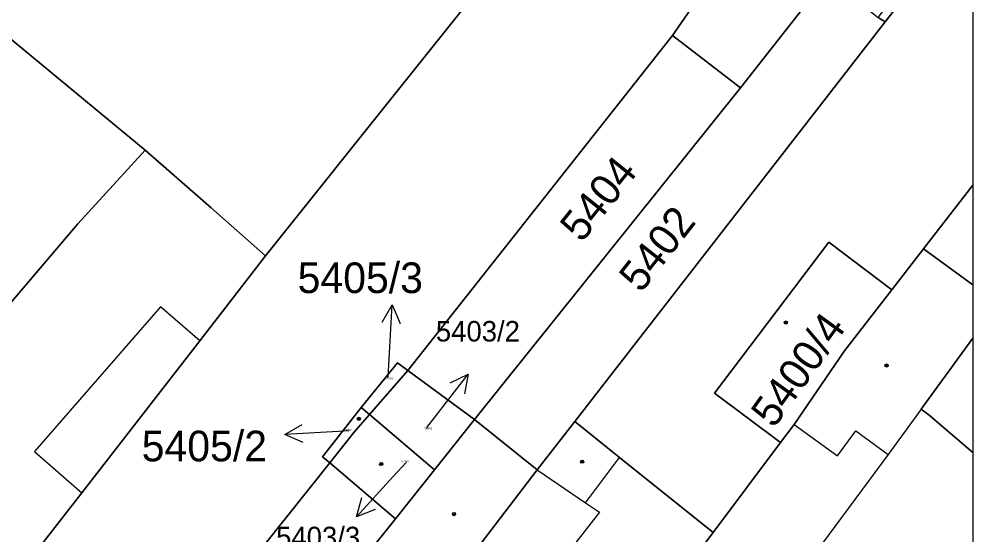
# Model space of a CAD drawing. Extents: x -596233 to -595156, y -1161235 to -1159375.
# Drawn here: x -595211.2 to -595158.2, y -1160883.5 to -1160854.9 of the extents above; entities that cross this region are included whole.
import ezdxf

# ---------------------------------------------------------------- set-up
doc = ezdxf.new("R2010")
doc.units = 0
for name, color, linetype in [('KN_CAR_KR', 7, 'Continuous'), ('KN_KULTURY', 7, 'Continuous'), ('KN_PARC_CIS_POM', 7, 'Continuous'), ('KN_PARC_CIS_POZ', 7, 'Continuous'), ('KN_PARC_CIS_STAV', 7, 'Continuous'), ('KN_PARC_PLOCHA', 7, 'Continuous'), ('PARC_C_SIPKA', 7, 'Continuous'), ('parcely_l', 7, 'Continuous')]:
    doc.layers.add(name, color=color, linetype=linetype)

msp = doc.modelspace()

# ---------------------------------------------------------------- linework, layer by layer
at = {"layer": 'KN_CAR_KR'}
for points in [[(-595203.31, -1160870.85), (-595210.3, -1160878.89)], [(-595201.13, -1160872.75), (-595203.31, -1160870.85)], [(-595161.1, -1160876.53), (-595162.94, -1160879.05)], [(-595168.15, -1160877.38), (-595165.75, -1160879.13)], [(-595165.75, -1160879.13), (-595164.73, -1160877.73)], [(-595164.73, -1160877.73), (-595162.94, -1160879.05)], [(-595210.3, -1160878.89), (-595207.67, -1160881.17)], [(-595179.73, -1160881.73), (-595177.83, -1160879.22)], [(-595162.94, -1160879.05), (-595174.72, -1160894.97)], [(-595182.4, -1160879.91), (-595179.73, -1160881.73)], [(-595179.73, -1160881.73), (-595178.94, -1160882.26)], [(-595178.94, -1160882.26), (-595188.92, -1160895.04)]]:
    msp.add_lwpolyline(points, dxfattribs=at)
at = {"layer": 'KN_KULTURY'}
for centre, radius in [((-595168.61, -1160871.73), 0.09), ((-595168.61, -1160871.73), 0.0398), ((-595163.02, -1160874.11), 0.09), ((-595163.02, -1160874.11), 0.0398), ((-595192.3, -1160877.07), 0.09), ((-595192.3, -1160877.07), 0.0398), ((-595191.06, -1160879.58), 0.09), ((-595191.06, -1160879.58), 0.0398), ((-595179.91, -1160879.45), 0.09), ((-595179.91, -1160879.45), 0.0398), ((-595187.02, -1160882.36), 0.09), ((-595187.02, -1160882.36), 0.0398)]:
    msp.add_circle(centre, radius, dxfattribs=at)
at = {"layer": 'KN_PARC_PLOCHA'}
for points in [[(-595158.2304, -1160833.5578), (-595169.34, -1160847.73), (-595174.9, -1160855.8), (-595189.59, -1160874.38), (-595190.16, -1160873.96), (-595192.17, -1160876.44), (-595194.31, -1160879.18), (-595193.91, -1160879.52), (-595201.27, -1160888.74), (-595207.27, -1160896.3), (-595216.06, -1160891.37), (-595210.02, -1160884.2), (-595207.67, -1160881.17), (-595201.13, -1160872.75), (-595197.47, -1160868.03), (-595181.99, -1160848.62), (-595180.09, -1160846.24), (-595173.37, -1160837.72), (-595168.7, -1160831.86), (-595164.04, -1160826), (-595159.37, -1160820.14), (-595158.2304, -1160818.7112)], [(-595193.38, -1160839.46), (-595185.77, -1160845.57), (-595181.99, -1160848.62), (-595197.47, -1160868.03), (-595200.5, -1160865.36), (-595204.15, -1160862.15), (-595211.84, -1160855.79), (-595218.88, -1160849.86), (-595220.43, -1160851.29), (-595224.67, -1160856), (-595227, -1160854.17), (-595228.57, -1160852.93), (-595225.27, -1160849.86), (-595204.53, -1160830.52)], [(-595158.2304, -1160837.6852), (-595158.42, -1160837.93), (-595160.07, -1160839.89), (-595161.73, -1160842.01), (-595163.37, -1160844.29), (-595165.02, -1160846.42), (-595166.67, -1160848.54), (-595168.44, -1160850.82), (-595166.29, -1160852.54), (-595171.12, -1160858.69), (-595174.9, -1160855.8), (-595169.34, -1160847.73), (-595158.2304, -1160833.5578)], [(-595158.2304, -1160848.8418), (-595163.09, -1160855.03), (-595163.48, -1160854.8), (-595161.67, -1160852.42), (-595160.02, -1160850.3), (-595158.37, -1160848.18), (-595158.2304, -1160847.9814)], [(-595158.2304, -1160864.1086), (-595160.97, -1160867.64), (-595162.73, -1160869.91), (-595166.23, -1160867.26), (-595172.57, -1160875.65), (-595168.9, -1160878.38), (-595172.65, -1160883.38), (-595177.83, -1160879.22), (-595180.32, -1160877.22), (-595163.09, -1160855.03), (-595158.2304, -1160848.8418)], [(-595163.48, -1160854.8), (-595163.09, -1160855.03), (-595180.32, -1160877.22), (-595182.4, -1160879.91), (-595185.88, -1160877.1), (-595171.12, -1160858.69), (-595166.29, -1160852.54)], [(-595204.15, -1160862.15), (-595207.89, -1160866.25), (-595223.93, -1160885.1), (-595231.86, -1160878.58), (-595217.35, -1160862.42), (-595217.51, -1160862.28), (-595211.84, -1160855.79)], [(-595171.12, -1160858.69), (-595185.88, -1160877.1), (-595189.59, -1160874.38), (-595174.9, -1160855.8)], [(-595197.47, -1160868.03), (-595201.13, -1160872.75), (-595207.67, -1160881.17), (-595210.02, -1160884.2), (-595216.06, -1160891.37), (-595223.93, -1160885.1), (-595207.89, -1160866.25), (-595204.15, -1160862.15), (-595200.5, -1160865.36)], [(-595158.2304, -1160864.1086), (-595158.2304, -1160869.6402), (-595160.97, -1160867.64)], [(-595162.73, -1160869.91), (-595165.36, -1160873.3), (-595168.15, -1160877.38), (-595168.9, -1160878.38), (-595172.57, -1160875.65), (-595166.23, -1160867.26)], [(-595158.2304, -1160869.6402), (-595158.2304, -1160872.6011), (-595161.1, -1160876.53), (-595160.66, -1160876.86), (-595158.2304, -1160878.9346), (-595158.2304, -1160894.6076), (-595160.01, -1160896.91), (-595162.85, -1160901.09), (-595168.12, -1160909.33), (-595168.15, -1160909.38), (-595188.26, -1160904.94), (-595182.91, -1160897.08), (-595176.06, -1160887.94), (-595172.65, -1160883.38), (-595168.9, -1160878.38), (-595168.15, -1160877.38), (-595165.36, -1160873.3), (-595162.73, -1160869.91), (-595160.97, -1160867.64)], [(-595158.2304, -1160872.6011), (-595158.2304, -1160878.9346), (-595160.66, -1160876.86), (-595161.1, -1160876.53)], [(-595189.59, -1160874.38), (-595191.71, -1160876.83), (-595192.17, -1160876.44), (-595190.16, -1160873.96)], [(-595185.88, -1160877.1), (-595188.11, -1160879.9), (-595191.71, -1160876.83), (-595189.59, -1160874.38)], [(-595191.71, -1160876.83), (-595192.57, -1160877.83), (-595193.91, -1160879.52), (-595194.31, -1160879.18), (-595192.17, -1160876.44)], [(-595182.4, -1160879.91), (-595188.33, -1160887.65), (-595192.94, -1160893.67), (-595197.93, -1160901.64), (-595202.6, -1160898.97), (-595197.02, -1160891.25), (-595195.01, -1160888.66), (-595194.06, -1160887.43), (-595191.99, -1160884.77), (-595190.27, -1160882.62), (-595188.11, -1160879.9), (-595185.88, -1160877.1)], [(-595188.11, -1160879.9), (-595190.27, -1160882.62), (-595193.91, -1160879.52), (-595192.57, -1160877.83), (-595191.71, -1160876.83)], [(-595172.65, -1160883.38), (-595176.06, -1160887.94), (-595182.91, -1160897.08), (-595188.26, -1160904.94), (-595197.93, -1160901.64), (-595192.94, -1160893.67), (-595188.33, -1160887.65), (-595182.4, -1160879.91), (-595180.32, -1160877.22), (-595177.83, -1160879.22)], [(-595190.27, -1160882.62), (-595191.99, -1160884.77), (-595194.06, -1160887.43), (-595195.01, -1160888.66), (-595197.02, -1160891.25), (-595202.6, -1160898.97), (-595207.27, -1160896.3), (-595201.27, -1160888.74), (-595193.91, -1160879.52)]]:
    msp.add_lwpolyline(points, close=True, dxfattribs=at)
at = {"layer": 'PARC_C_SIPKA'}
for points in [[(-595191.0002, -1160871.7138), (-595190.4417, -1160870.7453), (-595190.002, -1160871.7733)], [(-595190.68, -1160874.78), (-595190.62, -1160873.74), (-595190.4417, -1160870.7453)], [(-595188.52, -1160877.55), (-595188.06, -1160876.96), (-595186.2282, -1160874.5842)], [(-595187.2347, -1160875.0708), (-595186.2282, -1160874.5842), (-595186.4428, -1160875.6814)], [(-595195.3871, -1160878.3869), (-595196.4148, -1160877.9467), (-595195.446, -1160877.3886)], [(-595192.85, -1160877.74), (-595193.42, -1160877.77), (-595196.4148, -1160877.9467)], [(-595189.66, -1160879.47), (-595190.42, -1160880.29), (-595192.4297, -1160882.5174)], [(-595191.3886, -1160882.1099), (-595192.4297, -1160882.5174), (-595192.131, -1160881.44)]]:
    msp.add_lwpolyline(points, dxfattribs=at)
at = {"layer": 'parcely_l'}
for points in [[(-595158.2304, -1160833.5578), (-595169.34, -1160847.73), (-595174.9, -1160855.8)], [(-595197.47, -1160868.03), (-595181.99, -1160848.62)], [(-595158.2304, -1160848.8418), (-595163.09, -1160855.03)], [(-595158.2304, -1160848.8418), (-595158.2304, -1160864.1086)], [(-595171.12, -1160858.69), (-595166.29, -1160852.54)], [(-595163.09, -1160855.03), (-595163.48, -1160854.8)], [(-595180.32, -1160877.22), (-595163.09, -1160855.03)], [(-595211.84, -1160855.79), (-595204.15, -1160862.15)], [(-595174.9, -1160855.8), (-595189.59, -1160874.38)], [(-595174.9, -1160855.8), (-595171.12, -1160858.69)], [(-595185.88, -1160877.1), (-595171.12, -1160858.69)], [(-595223.93, -1160885.1), (-595207.89, -1160866.25), (-595204.15, -1160862.15)], [(-595204.15, -1160862.15), (-595200.5, -1160865.36), (-595197.47, -1160868.03)], [(-595158.2304, -1160864.1086), (-595160.97, -1160867.64)], [(-595158.2304, -1160864.1086), (-595158.2304, -1160869.6402)], [(-595168.9, -1160878.38), (-595172.57, -1160875.65), (-595166.23, -1160867.26), (-595162.73, -1160869.91)], [(-595197.47, -1160868.03), (-595201.13, -1160872.75), (-595207.67, -1160881.17), (-595210.02, -1160884.2), (-595216.06, -1160891.37)], [(-595160.97, -1160867.64), (-595162.73, -1160869.91)], [(-595160.97, -1160867.64), (-595158.2304, -1160869.6402)], [(-595158.2304, -1160869.6402), (-595158.2304, -1160872.6011)], [(-595162.73, -1160869.91), (-595165.36, -1160873.3), (-595168.15, -1160877.38), (-595168.9, -1160878.38)], [(-595158.2304, -1160872.6011), (-595161.1, -1160876.53), (-595160.66, -1160876.86), (-595158.2304, -1160878.9346)], [(-595158.2304, -1160872.6011), (-595158.2304, -1160878.9346)], [(-595189.59, -1160874.38), (-595190.16, -1160873.96), (-595192.17, -1160876.44)], [(-595191.71, -1160876.83), (-595189.59, -1160874.38)], [(-595189.59, -1160874.38), (-595185.88, -1160877.1)], [(-595192.17, -1160876.44), (-595194.31, -1160879.18), (-595193.91, -1160879.52)], [(-595192.17, -1160876.44), (-595191.71, -1160876.83)], [(-595193.91, -1160879.52), (-595192.57, -1160877.83), (-595191.71, -1160876.83)], [(-595191.71, -1160876.83), (-595188.11, -1160879.9)], [(-595185.88, -1160877.1), (-595188.11, -1160879.9)], [(-595182.4, -1160879.91), (-595185.88, -1160877.1)], [(-595182.4, -1160879.91), (-595180.32, -1160877.22)], [(-595180.32, -1160877.22), (-595177.83, -1160879.22), (-595172.65, -1160883.38)], [(-595168.9, -1160878.38), (-595172.65, -1160883.38)], [(-595158.2304, -1160878.9346), (-595158.2304, -1160894.6076)], [(-595193.91, -1160879.52), (-595201.27, -1160888.74), (-595207.27, -1160896.3)], [(-595190.27, -1160882.62), (-595193.91, -1160879.52)], [(-595197.93, -1160901.64), (-595192.94, -1160893.67), (-595188.33, -1160887.65), (-595182.4, -1160879.91)], [(-595188.11, -1160879.9), (-595190.27, -1160882.62)], [(-595202.6, -1160898.97), (-595197.02, -1160891.25), (-595195.01, -1160888.66), (-595194.06, -1160887.43), (-595191.99, -1160884.77), (-595190.27, -1160882.62)], [(-595172.65, -1160883.38), (-595176.06, -1160887.94), (-595182.91, -1160897.08), (-595188.26, -1160904.94)]]:
    msp.add_lwpolyline(points, dxfattribs=at)

# ---------------------------------------------------------------- texts
at = {"layer": 'KN_PARC_CIS_POM'}
for s, p in [('5405/3', (-595190.8133, -1160874.88)), ('5405/2', (-595193.1333, -1160877.74)), ('5403/2', (-595188.6533, -1160877.65)), ('5403/3', (-595189.9433, -1160879.47))]:
    msp.add_text(s, height=0.1, dxfattribs=at).set_placement(p)
at = {"layer": 'KN_PARC_CIS_POZ'}
for s, rotation, p in [('5404', 51.29966, (-595179.9387, -1160867.3423)), ('5402', 51.94973, (-595176.6509, -1160870.1343))]:
    msp.add_text(s, height=1.7, rotation=rotation, dxfattribs=at).set_placement(p)
for s, height, p in [('5405/3', 1.7, (-595195.6966, -1160870.09)), ('5403/2', 1.14, (-595188.0252, -1160872.7787))]:
    msp.add_text(s, height=height, dxfattribs=at).set_placement(p)
at = {"layer": 'KN_PARC_CIS_STAV'}
msp.add_text('5400/4', height=1.7, rotation=54.19904, dxfattribs=at).set_placement((-595169.2776, -1160877.6465))
for s, height, p in [('5405/2', 1.7, (-595204.3466, -1160879.43)), ('5403/3', 1.14, (-595196.8892, -1160884.2004))]:
    msp.add_text(s, height=height, dxfattribs=at).set_placement(p)

doc.saveas('drawing.dxf')
